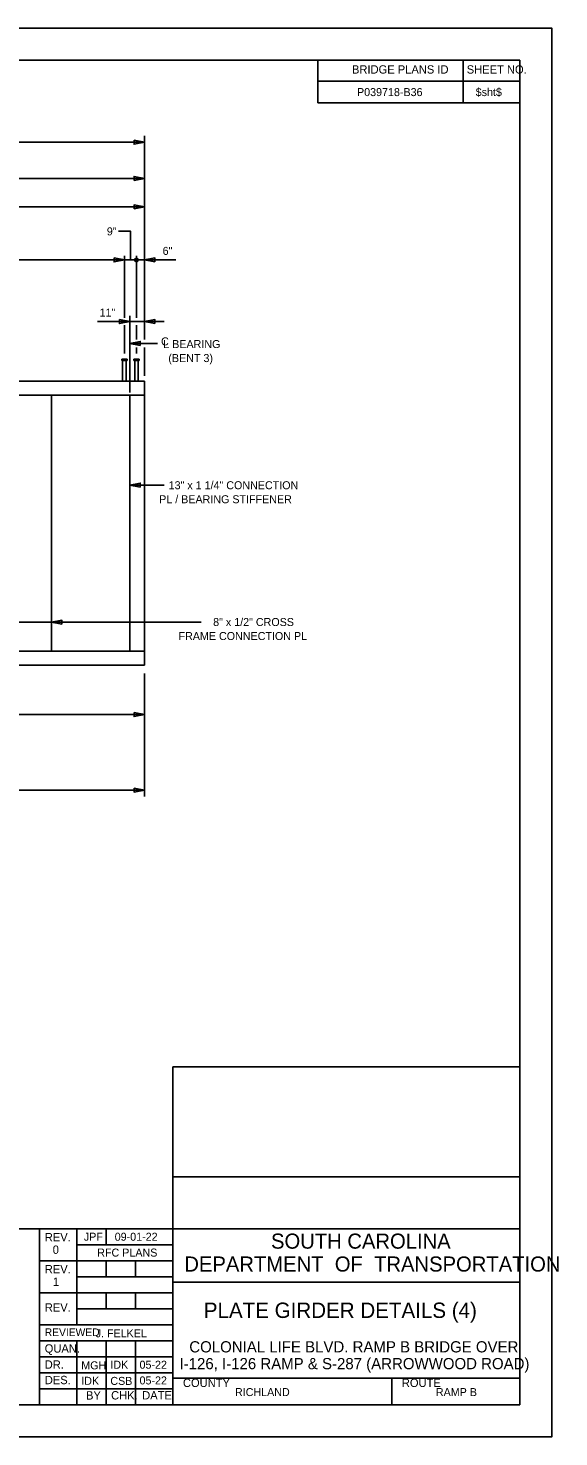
# Model space of a CAD drawing. Extents: x -305 to -161, y -187 to -99.
# Drawn here: x -193.9 to -160.8, y -187.5 to -99.5 of the extents above; entities that cross this region are included whole.
import ezdxf

# ---------------------------------------------------------------- set-up
doc = ezdxf.new("R2010")
doc.units = 0
for name, color, linetype in [('BR_AUTO DIMENSION', 7, 'Continuous'), ('BR_BORDER LINES', 7, 'Continuous'), ('BR_CENTER LINES', 7, 'Continuous'), ('BR_STRUCTURAL STEEL', 7, 'Continuous'), ('BR_TEXT', 7, 'Continuous'), ('Default', 7, 'Continuous'), ('Level 31', 7, 'Continuous')]:
    doc.layers.add(name, color=color, linetype=linetype)

msp = doc.modelspace()

# ---------------------------------------------------------------- linework, layer by layer
at = {"layer": 'BR_AUTO DIMENSION'}
for p, q in [((-186.619, -118.929), (-186.619, -106.206)), ((-284.433, -106.618), (-186.619, -106.618)), ((-228.974, -108.876), (-186.619, -108.876)), ((-186.619, -110.653), (-207.723, -110.653)), ((-223.557, -113.971), (-187.869, -113.971)), ((-187.869, -117.593), (-187.869, -113.71)), ((-184.666, -113.971), (-187.869, -113.971)), ((-187.119, -117.593), (-187.119, -113.71)), ((-189.54, -117.821), (-185.396, -117.821)), ((-187.869, -119.81), (-187.869, -118.048)), ((-187.119, -118.929), (-187.119, -118.048)), ((-187.536, -119.183), (-185.813, -119.183)), ((-187.119, -119.81), (-187.119, -119.447)), ((-186.619, -121.218), (-186.619, -119.447)), ((-187.536, -128.037), (-185.378, -128.037)), ((-223.369, -136.601), (-183.069, -136.601)), ((-186.619, -139.795), (-186.619, -147.486)), ((-186.619, -142.367), (-217.973, -142.367)), ((-207.723, -147.085), (-186.619, -147.085))]:
    msp.add_line(p, q, dxfattribs=at)
for points in [[(-187.269, -106.493), (-186.619, -106.618), (-187.269, -106.743)], [(-187.269, -109.001), (-186.619, -108.876), (-187.269, -108.751)], [(-187.269, -110.778), (-186.619, -110.653), (-187.269, -110.528)], [(-188.519, -113.846), (-187.869, -113.971), (-188.519, -114.096)], [(-185.969, -114.096), (-186.619, -113.971), (-185.969, -113.846)], [(-188.186, -117.696), (-187.536, -117.821), (-188.186, -117.946)], [(-185.969, -117.946), (-186.619, -117.821), (-185.969, -117.696)], [(-186.886, -119.308), (-187.536, -119.183), (-186.886, -119.058)], [(-186.886, -128.162), (-187.536, -128.037), (-186.886, -127.912)], [(-191.768, -136.726), (-192.418, -136.601), (-191.768, -136.476)], [(-187.269, -142.242), (-186.619, -142.367), (-187.269, -142.492)], [(-187.269, -146.96), (-186.619, -147.085), (-187.269, -147.21)]]:
    msp.add_lwpolyline(points, close=True, dxfattribs=at)
msp.add_lwpolyline([(-187.494, -113.971), (-187.494, -112.165), (-188.234, -112.165)], dxfattribs=at)
msp.add_circle((-187.119, -113.971), 0.111, dxfattribs=at)
at = {"layer": 'BR_BORDER LINES'}
for p, q in [((-163.178, -101.489), (-297.843, -101.489)), ((-175.788, -104.156), (-175.788, -101.489)), ((-166.722, -104.156), (-166.722, -101.489)), ((-163.178, -185.489), (-163.178, -101.489)), ((-175.788, -102.808), (-163.178, -102.808)), ((-166.722, -102.808), (-163.178, -102.808)), ((-163.178, -104.156), (-175.788, -104.156)), ((-184.846, -185.489), (-184.846, -164.383)), ((-184.846, -164.383), (-163.178, -164.383)), ((-184.845, -171.242), (-163.178, -171.242)), ((-214.64, -174.489), (-193.18, -174.489)), ((-193.18, -185.489), (-193.18, -174.489)), ((-193.18, -174.489), (-163.178, -174.489)), ((-190.846, -174.489), (-190.846, -180.489)), ((-189.013, -175.489), (-189.013, -174.489)), ((-190.846, -175.489), (-184.846, -175.489)), ((-193.18, -176.489), (-184.846, -176.489)), ((-189.013, -177.489), (-189.013, -176.489)), ((-187.179, -177.489), (-187.179, -176.489)), ((-190.846, -177.489), (-184.846, -177.489)), ((-193.18, -178.489), (-184.846, -178.489)), ((-189.013, -179.489), (-189.013, -178.489)), ((-187.179, -179.489), (-187.179, -178.489)), ((-184.846, -177.822), (-184.846, -177.822)), ((-184.846, -177.823), (-163.178, -177.823)), ((-190.846, -179.489), (-184.846, -179.489)), ((-193.18, -180.489), (-184.846, -180.489)), ((-193.18, -181.489), (-184.846, -181.489)), ((-190.846, -181.489), (-190.846, -185.489)), ((-189.013, -181.489), (-189.013, -185.489)), ((-187.179, -181.489), (-187.179, -185.489)), ((-193.18, -182.489), (-184.846, -182.489)), ((-193.18, -183.489), (-184.846, -183.489)), ((-184.846, -183.823), (-163.178, -183.823)), ((-184.456, -183.823), (-163.178, -183.823)), ((-171.179, -185.489), (-171.179, -183.823)), ((-193.18, -184.489), (-184.846, -184.489)), ((-297.843, -185.489), (-163.178, -185.489))]:
    msp.add_line(p, q, dxfattribs=at)
at = {"layer": 'BR_CENTER LINES'}
msp.add_line((-187.536, -117.463), (-187.536, -122.256), dxfattribs=at)
at = {"layer": 'BR_STRUCTURAL STEEL'}
for p, q in [((-186.619, -121.537), (-207.723, -121.537)), ((-186.619, -121.537), (-186.619, -122.412)), ((-186.619, -122.412), (-284.433, -122.412)), ((-192.418, -138.412), (-192.418, -122.412)), ((-187.536, -122.412), (-187.536, -138.412)), ((-186.619, -122.412), (-186.619, -138.412)), ((-186.619, -138.412), (-284.433, -138.412)), ((-186.619, -139.287), (-186.619, -138.412)), ((-186.619, -139.287), (-207.723, -139.287))]:
    msp.add_line(p, q, dxfattribs=at)
at = {"layer": 'Default'}
for p, q in [((-188.041, -120.162), (-188.041, -120.256)), ((-188.041, -120.162), (-187.697, -120.162)), ((-188.041, -120.256), (-187.697, -120.256)), ((-187.979, -120.256), (-187.979, -121.537)), ((-187.76, -120.256), (-187.76, -121.537)), ((-187.697, -120.162), (-187.697, -120.256)), ((-187.291, -120.162), (-187.291, -120.256)), ((-187.291, -120.162), (-186.947, -120.162)), ((-187.291, -120.256), (-186.947, -120.256)), ((-187.229, -120.256), (-187.229, -121.537)), ((-187.01, -120.256), (-187.01, -121.537)), ((-186.947, -120.162), (-186.947, -120.256))]:
    msp.add_line(p, q, dxfattribs=at)
at = {"layer": 'Level 31'}
msp.add_line((-174.011, -179.583), (-174.011, -179.583), dxfattribs=at)
msp.add_lwpolyline([(-305.176, -187.489), (-161.176, -187.489), (-161.176, -99.489), (-305.176, -99.489)], close=True, dxfattribs=at)

# ---------------------------------------------------------------- texts
at = {"layer": 'BR_AUTO DIMENSION'}
for s, p in [('9"', (-188.966, -112.433)), ('6"', (-185.484, -113.652)), ('11"', (-189.422, -117.502))]:
    msp.add_text(s, height=0.5, rotation=360, dxfattribs=at).set_placement(p)
at = {"layer": 'BR_TEXT'}
for s, height, p in [('BRIDGE PLANS ID', 0.52, (-173.663, -102.327)), ('SHEET NO.', 0.52, (-166.499, -102.327)), ('P039718-B36', 0.5, (-173.348, -103.732)), ('$sht$', 0.5, (-165.939, -103.732)), ('C', 0.5, (-185.58, -119.306)), ('L BEARING', 0.5, (-185.445, -119.473)), ('(BENT 3)', 0.5, (-185.127, -120.348)), ('13" x 1 1/4" CONNECTION ', 0.5, (-185.108, -128.293)), ('PL / BEARING STIFFENER', 0.5, (-185.701, -129.168)), ('8" x 1/2" CROSS ', 0.5, (-182.33, -136.838)), ('FRAME CONNECTION PL', 0.5, (-184.491, -137.713)), ('REV.', 0.52, (-192.841, -175.277)), ('JPF', 0.5, (-190.4, -175.239)), ('09-01-22', 0.5, (-188.475, -175.239)), ('SOUTH CAROLINA', 0.94348, (-178.718, -175.735)), ('0', 0.52, (-192.345, -176.057)), ('RFC PLANS', 0.5, (-189.566, -176.229)), ('REV.', 0.52, (-192.841, -177.277)), ('DEPARTMENT  OF  TRANSPORTATION', 0.94348, (-184.129, -177.166)), ('1', 0.52, (-192.337, -178.057)), ('REV.', 0.52, (-192.841, -179.667)), ('PLATE GIRDER DETAILS (4)', 0.96, (-182.913, -180.063)), ('REVIEWED', 0.48, (-192.843, -181.195)), ('J. FELKEL', 0.5, (-189.664, -181.272)), ('QUAN.', 0.52, (-192.846, -182.229)), ('COLONIAL LIFE BLVD. RAMP B BRIDGE OVER', 0.7, (-183.82, -182.216)), ('DR.', 0.52, (-192.845, -183.235)), ('MGH', 0.5, (-190.563, -183.274)), ('IDK', 0.5, (-188.747, -183.234)), ('05-22', 0.5, (-186.926, -183.234)), ('I-126, I-126 RAMP & S-287 (ARROWWOOD ROAD) ', 0.7, (-184.429, -183.266)), ('DES.', 0.52, (-192.841, -184.2)), ('IDK', 0.5, (-190.563, -184.24)), ('CSB', 0.5, (-188.747, -184.246)), ('05-22', 0.5, (-186.926, -184.215)), ('COUNTY', 0.52, (-184.217, -184.376)), ('ROUTE', 0.52, (-170.55, -184.376)), ('BY', 0.52, (-190.265, -185.161)), ('CHK.', 0.52, (-188.701, -185.156)), ('DATE', 0.52, (-186.761, -185.156)), ('RICHLAND', 0.5, (-180.968, -184.944)), ('RAMP B', 0.5, (-168.424, -184.944))]:
    msp.add_text(s, height=height, dxfattribs=at).set_placement(p)

doc.saveas('drawing.dxf')
